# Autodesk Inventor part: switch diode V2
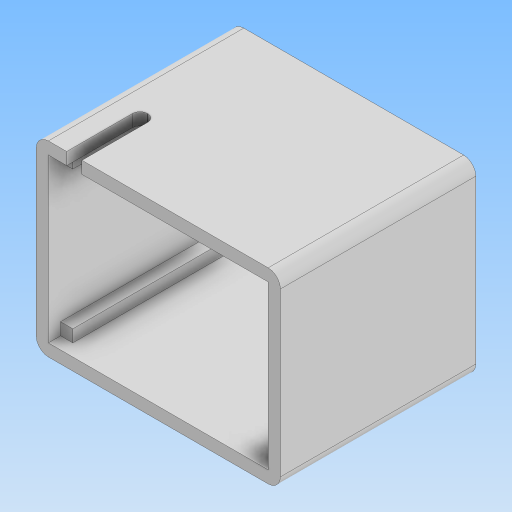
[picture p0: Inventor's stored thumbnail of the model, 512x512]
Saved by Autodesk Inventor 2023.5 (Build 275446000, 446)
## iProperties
Created: 2025-12
Part Number: switch diode V2
Material: Générique
Document SubType Name: Modeling
Designer: admin
Density: 1 g/cm^3
Appearance: Par défaut
Author: admin
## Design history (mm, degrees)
sketch "Esquisse1"
  geometry: L1 (28.6, 5.2)-(28.6, -5.2); L2 (-2.787, 5.2)-(2.787, 5.2); L3 (17.213, 5.2)-(22.787, 5.2); L4 (28.6, -5.2)-(17.213, -5.2); L5 (2.787, -5.2)-(-2.787, -5.2); L6 (-10, 20.648)-(30, 20.648); L7 (30, 20.648)-(30, -10); L8 (30, -10)-(-10, -10); L9 (-10, -10)-(-10, 20.648); L10 (20, 0)-(0, 0); L11 (10, 0)-(10, 20.648); C1 r 3.2 at (10, 12); A1 r 5.9 centre (0, 0) between (-2.787, 5.2) and (-2.787, -5.2); A2 r 5.9 centre (0, 0) between (2.787, -5.2) and (2.787, 5.2); A3 r 5.9 centre (20, 0) between (22.787, -5.2) and (22.787, 5.2); A4 r 5.9 centre (20, 0) between (17.213, 5.2) and (17.213, -5.2); 1 further point
  constraints: 22 end point, 8 point on circle, 6 parallel, 5 centre point, 3 horizontal, 3 perpendicular, 2 midpoint, 2 point on line, 1 coincident
  dimensions: "d2" = 20 distance of L10.start point (0, 0); "d3" = 10.4 distance of L1.start L1.end; "d5" = 0 vertical distance of point (0, 0) L10.start; "d6" = 40 distance of L7.end L8.end; "d7" = 10 distance from line of L10.end L9; "d8" = 10 distance from line of L7 L10.start (derived); "d9" = 10 distance from line of L8 point (0, 0); "d10" = 6.4 diameter of C1; "d11" = 12 vertical distance of point (0, 0) C1.centre
extrude "Extrusion1" new body sketch "Esquisse1" distance "d12" = 2; taper "d13" = 0 deg
sketch "Esquisse2"
  geometry: L1 (-10, -10)-(30, -10) reference; L2 (30, -10)-(30, 20.648) reference; L3 (30, 20.648)-(-10, 20.648) reference; L4 (-10, 20.648)-(-10, -10) reference; L5 (2.787, -5.2)-(-2.787, -5.2) reference; L6 (-2.787, 5.2)-(2.787, 5.2) reference; L7 (22.787, -5.2)-(17.213, -5.2) reference; L8 (17.213, 5.2)-(22.787, 5.2) reference; L9 (-8, 18.648)-(28, 18.648); L10 (28, 18.648)-(28, -8); L11 (28, -8)-(-8, -8); L12 (-8, -8)-(-8, 18.648); C1 r 3.2 at (10, 12) reference; A1 r 5.9 centre (0, 0) between (-2.787, 5.2) and (-2.787, -5.2) reference; A2 r 5.9 centre (0, 0) between (2.787, -5.2) and (2.787, 5.2) reference; A3 r 5.9 centre (20, 0) between (17.213, 5.2) and (17.213, -5.2) reference; A4 r 5.9 centre (20, 0) between (22.787, -5.2) and (22.787, 5.2) reference; 1 further point
  constraints: 8 end point, 2 parallel, 1 horizontal, 1 perpendicular
  dimensions: "d14" = 2 distance between parallel lines of L1 L11; "d15" = 2 distance between parallel lines of L2 L10; "d16" = 2 distance between parallel lines of L4 L12; "d17" = 2 distance between parallel lines of L3 L9
extrude "Extrusion2" join sketch "Esquisse2" distance "d18" = 30; taper "d19" = 0 deg
sketch "Esquisse3"
  geometry: L1 (40, -32)-(0, -32) reference; L2 (5, -32)-(7.5, -32); L3 (7.5, -32)-(7.5, -20); L4 (7.5, -20)-(5, -20); L5 (5, -20)-(5, -32); L6 (0, 0)-(0, -32) reference; 2 further points
  constraints: 8 end point, 2 parallel, 1 horizontal, 1 perpendicular, 1 point on line
  dimensions: "d20" = 2.5 distance of L3.end L4.end; "d21" = 12 distance of L4.end L2.start; "d47" = 5 distance between parallel lines of L6 L5
extrude "Extrusion3" cut sketch "Esquisse3" distance "d22" = 5; taper "d23" = 0 deg
fillet "Congé1" dims "d24" = 1.2
sketch "Esquisse4"
  geometry: L1 (10, -10)-(-30, -10) reference; L2 (10, 20.648)-(10, -10) reference; L3 (-30, 20.648)-(10, 20.648) reference; L4 (-30, -10)-(-30, 20.648) reference; L5 (-2.787, -5.2)-(2.787, -5.2) reference; L6 (2.787, 5.2)-(-2.787, 5.2) reference; L7 (-22.787, -5.2)-(-17.213, -5.2) reference; L8 (-17.213, 5.2)-(-22.787, 5.2) reference; L9 (-25.991, 15.856)-(-23.242, 15.856); L10 (-23.242, 15.856)-(-23.242, 12.744); L11 (-23.242, 12.744)-(-25.991, 12.744); L12 (-25.991, 12.744)-(-25.991, 15.856); L13 (2.122, 12.609)-(2.122, 15.87); L14 (2.122, 15.87)-(4.871, 15.87); L15 (4.871, 15.87)-(4.871, 12.609); L16 (4.871, 12.609)-(2.122, 12.609); C1 r 3.2 at (-10, 12) reference; A1 r 5.9 centre (0, 0) between (-2.787, 5.2) and (-2.787, -5.2) reference; A2 r 5.9 centre (0, 0) between (2.787, -5.2) and (2.787, 5.2) reference; A3 r 5.9 centre (-20, 0) between (-22.787, 5.2) and (-22.787, -5.2) reference; A4 r 5.9 centre (-20, 0) between (-17.213, -5.2) and (-17.213, 5.2) reference; 1 further point
  constraints: 4 other
extrude "Extrusion4" cut sketch "Esquisse4" extent not by distance; stored distance "d25" = 0; taper "d26" = 0 deg
sketch "Esquisse5"
  geometry: L1 (20.428, 12.029)-(20.428, 15.856) reference; L2 (20.428, 15.856)-(21.936, 15.856) reference; L3 (21.936, 15.856)-(21.936, 12.112) reference; L4 (23.949, 12.112)-(23.949, 15.856) reference; L5 (23.949, 15.856)-(25.456, 15.856) reference; L6 (25.456, 15.856)-(25.456, 12.024) reference; L7 (-5.73, 9.87)-(-5.73, 10.916) reference; L8 (-5.73, 10.916)-(-4.869, 10.916) reference; L9 (-4.869, 10.916)-(-4.869, 14.825) reference; L10 (-4.869, 14.825)-(-5.73, 14.825) reference; L11 (-5.73, 14.825)-(-5.73, 15.87) reference; L12 (-5.73, 15.87)-(-2.501, 15.87) reference; L13 (-2.501, 15.87)-(-2.501, 14.825) reference; L14 (-2.501, 14.825)-(-3.362, 14.825) reference; L15 (-3.362, 14.825)-(-3.362, 10.916) reference; L16 (-3.362, 10.916)-(-2.501, 10.916) reference; L17 (-2.501, 10.916)-(-2.501, 9.87) reference; L18 (-2.501, 9.87)-(-5.73, 9.87) reference; L19 (-8, 18.648)-(-8, -8) reference; L20 (-8, -8)-(28, -8) reference; L21 (28, -8)-(28, 18.648) reference; L22 (28, 18.648)-(-8, 18.648) reference; L23 (2.787, -5.2)-(-2.787, -5.2) reference; L24 (-2.787, 5.2)-(2.787, 5.2) reference; L25 (22.787, -5.2)-(17.213, -5.2) reference; L26 (17.213, 5.2)-(22.787, 5.2) reference; L27 (15, 6.2)-(5, 6.2); L28 (5, 6.2)-(5, 17.8); L29 (5, 17.8)-(15, 17.8); L30 (15, 17.8)-(15, 6.2); L31 (28, 18.648)-(-8, 18.648) reference; L32 (15.5, 17.8)-(4.5, 17.8); L33 (4.5, 17.8)-(4.5, 18.648); L34 (4.5, 18.648)-(15.5, 18.648); L35 (15.5, 18.648)-(15.5, 17.8); L36 (15.5, 6.2)-(4.5, 6.2); L37 (4.5, 6.2)-(4.5, 4.2); L38 (4.5, 4.2)-(15.5, 4.2); L39 (15.5, 4.2)-(15.5, 6.2); C1 r 3.2 at (10, 12) reference; A1 r 5.9 centre (0, 0) between (-2.787, 5.2) and (-2.787, -5.2) reference; A2 r 5.9 centre (0, 0) between (2.787, -5.2) and (2.787, 5.2) reference; A3 r 5.9 centre (20, 0) between (17.213, 5.2) and (17.213, -5.2) reference; A4 r 5.9 centre (20, 0) between (22.787, -5.2) and (22.787, 5.2) reference; 11 further points
  constraints: 24 end point, 6 parallel, 3 horizontal, 3 perpendicular, 3 point on line, 2 midpoint, 4 other
  dimensions: "d27" = 11.6 distance of L27.end L28.end; "d28" = 5.8 distance from line of L27 C1.centre (= 0.5 x d27); "d29" = 10 distance of L28.end L29.end; "d30" = 5 distance from line of C1.centre L30 (= 0.5 x d29); "d31" = 2 distance between parallel lines of L27 L38; "d32" = 11 distance of L37.end L38.end; "d33" = 11 distance of L32.start L32.end; "d34" = 5.5 horizontal distance of C1.centre point (4.5, 18.224) (= 0.5 x d33); "d35" = 5.5 horizontal distance of C1.centre point (15.5, 5.2) (= 0.5 x d32)
extrude "Extrusion5" join sketch "Esquisse5" distance "d36" = 13; taper "d37" = 0 deg
sketch "Esquisse6"
  geometry: L1 (22.787, -5.2)-(17.213, -5.2) reference; L2 (17.213, 5.2)-(22.787, 5.2) reference; L3 (2.787, -5.2)-(-2.787, -5.2) reference; L4 (-2.787, 5.2)-(2.787, 5.2) reference; L5 (15.5, 18.648)-(15.5, 17.8) reference; L6 (15.5, 17.8)-(4.5, 17.8) reference; L7 (4.5, 17.8)-(4.5, 18.648) reference; L8 (4.5, 18.648)-(-8, 18.648) reference; L9 (-8, 18.648)-(-8, -8) reference; L10 (-8, -8)-(28, -8) reference; L11 (28, -8)-(28, 18.648) reference; L12 (28, 18.648)-(15.5, 18.648) reference; L13 (-5.73, 9.87)-(-5.73, 10.916) reference; L14 (-5.73, 10.916)-(-4.869, 10.916) reference; L15 (-4.869, 10.916)-(-4.869, 14.825) reference; L16 (-4.869, 14.825)-(-5.73, 14.825) reference; L17 (-5.73, 14.825)-(-5.73, 15.87) reference; L18 (-5.73, 15.87)-(-2.501, 15.87) reference; L19 (-2.501, 15.87)-(-2.501, 14.825) reference; L20 (-2.501, 14.825)-(-3.362, 14.825) reference; L21 (-3.362, 14.825)-(-3.362, 10.916) reference; L22 (-3.362, 10.916)-(-2.501, 10.916) reference; L23 (-2.501, 10.916)-(-2.501, 9.87) reference; L24 (-2.501, 9.87)-(-5.73, 9.87) reference; L25 (20.428, 12.029)-(20.428, 15.856) reference; L26 (20.428, 15.856)-(21.936, 15.856) reference; L27 (21.936, 15.856)-(21.936, 12.112) reference; L28 (23.949, 12.112)-(23.949, 15.856) reference; L29 (23.949, 15.856)-(25.456, 15.856) reference; L30 (25.456, 15.856)-(25.456, 12.024) reference; L31 (15.5, 6.2)-(15.5, 4.2) reference; L32 (15.5, 4.2)-(4.5, 4.2) reference; L33 (4.5, 4.2)-(4.5, 6.2) reference; L34 (4.5, 6.2)-(15.5, 6.2) reference; L35 (4.5, 17.8)-(15.5, 17.8); L36 (15.5, 17.8)-(15.5, 6.2); L37 (15.5, 6.2)-(4.5, 6.2); L38 (4.5, 6.2)-(4.5, 17.8); C1 r 3.2 at (10, 12) reference; C2 r 3.2 at (10, 12) reference; A1 r 5.9 centre (20, 0) between (17.213, 5.2) and (17.213, -5.2) reference; A2 r 5.9 centre (20, 0) between (22.787, -5.2) and (22.787, 5.2) reference; A3 r 5.9 centre (0, 0) between (-2.787, 5.2) and (-2.787, -5.2) reference; A4 r 5.9 centre (0, 0) between (2.787, -5.2) and (2.787, 5.2) reference; 5 further points
  constraints: 8 end point, 2 parallel, 1 horizontal, 1 perpendicular, 4 other
extrude "Extrusion6" join sketch "Esquisse6" distance "d38" = 4; taper "d39" = 0 deg
sketch "Esquisse7"
  geometry: L1 (-8, 18.648)-(-8, -8) reference; L2 (-8, -8)-(-6, -8); L3 (-6, -8)-(-6, -6); L4 (-6, -6)-(-8, -6); L5 (-8, -6)-(-8, -8); L6 (-8, 18.648)-(-6, 18.648); L7 (-6, 18.648)-(-6, 16.648); L8 (-6, 16.648)-(-8, 16.648); L9 (-8, 16.648)-(-8, 18.648); L10 (28, -8)-(28, 18.648) reference; L11 (28, -8)-(26, -8); L12 (26, -8)-(26, -6); L13 (26, -6)-(28, -6); L14 (28, -6)-(28, -8); L15 (28, 18.648)-(26, 18.648); L16 (26, 18.648)-(26, 16.648); L17 (26, 16.648)-(28, 16.648); L18 (28, 16.648)-(28, 18.648); 6 further points
  constraints: 32 end point, 8 parallel, 4 horizontal, 4 perpendicular, 2 point on line
  dimensions: "d40" = 2 distance of L4.end L3.end; "d41" = 2 distance of L7.end L8.end; "d42" = 2 distance of L2.end L3.end; "d43" = 2 distance of L6.end L7.end; "d44" = 2 distance of L12.end L13.end
extrude "Extrusion7" join sketch "Esquisse7" distance "d45" = 28; taper "d46" = 0 deg
fillet "Congé2" dims "d48" = 2
sketch "Esquisse8"
  geometry: L1 (-3, -6)-(-3, -7); L2 (-17, -7)-(-17, -6); L3 (-15.5, 4.2)-(-4.5, 4.2) reference; L4 (10, 18.648)-(10, -8) reference; L5 (-28, 20.648)-(8, 20.648) reference; L6 (-30, -8)-(-30, 18.648) reference; L7 (8, -10)-(-28, -10) reference; L8 (-25.456, 12.024)-(-25.456, 15.856) reference; L9 (-25.456, 15.856)-(-23.949, 15.856) reference; L10 (-23.949, 15.856)-(-23.949, 12.112) reference; L11 (-21.936, 12.112)-(-21.936, 15.856) reference; L12 (-21.936, 15.856)-(-20.428, 15.856) reference; L13 (-20.428, 15.856)-(-20.428, 12.029) reference; L14 (5.73, 10.916)-(5.73, 9.87) reference; L15 (5.73, 9.87)-(2.501, 9.87) reference; L16 (2.501, 9.87)-(2.501, 10.916) reference; L17 (2.501, 10.916)-(3.362, 10.916) reference; L18 (3.362, 10.916)-(3.362, 14.825) reference; L19 (3.362, 14.825)-(2.501, 14.825) reference; L20 (2.501, 14.825)-(2.501, 15.87) reference; L21 (2.501, 15.87)-(5.73, 15.87) reference; L22 (5.73, 15.87)-(5.73, 14.825) reference; L23 (5.73, 14.825)-(4.869, 14.825) reference; L24 (4.869, 14.825)-(4.869, 10.916) reference; L25 (4.869, 10.916)-(5.73, 10.916) reference; L26 (-2.787, -5.2)-(2.787, -5.2) reference; L27 (2.787, 5.2)-(-2.787, 5.2) reference; L28 (-22.787, -5.2)-(-17.213, -5.2) reference; L29 (-17.213, 5.2)-(-22.787, 5.2) reference; L30 (-12, -9)-(-8.908, -7); L31 (-8.908, -6)-(-12, -4); L32 (-8.908, -4)-(-7.908, -4); L33 (-7.908, -9)-(-8.908, -9); L34 (-17, -6)-(-12, -6); L35 (-12, -4)-(-12, -6); L36 (-12, -7)-(-12, -9); L37 (-12, -7)-(-17, -7); L38 (-8.908, -9)-(-8.908, -7); L39 (-8.908, -6)-(-8.908, -4); L40 (-7.908, -4)-(-7.908, -6); L41 (-7.908, -7)-(-7.908, -9); L42 (-8.908, -6)-(-8.908, -6); L43 (-7.908, -6)-(-3, -6); L44 (-3, -7)-(-7.908, -7); C1 r 3.2 at (-10, 12) reference; A1 r 2 centre (8, -8) between (8, -10) and (10, -8) reference; A2 r 2 centre (8, 18.648) between (10, 18.648) and (8, 20.648) reference; A3 r 2 centre (-28, 18.648) between (-28, 20.648) and (-30, 18.648) reference; A4 r 2 centre (-28, -8) between (-30, -8) and (-28, -10) reference; A5 r 5.9 centre (0, 0) between (-2.787, 5.2) and (-2.787, -5.2) reference; A6 r 5.9 centre (0, 0) between (2.787, -5.2) and (2.787, 5.2) reference; A7 r 5.9 centre (-20, 0) between (-22.787, 5.2) and (-22.787, -5.2) reference; A8 r 5.9 centre (-20, 0) between (-17.213, -5.2) and (-17.213, 5.2) reference; 6 further points; 1 other entity
  constraints: 34 end point, 12 parallel, 7 horizontal, 5 perpendicular, 2 vertical, 1 coincident, 1 midpoint, 6 other
  dimensions: "d50" = 14 distance of L1.end L2.start; "d54" = 5 distance of L31.end L30.start; "d55" = 2.5 vertical distance of L31.end point (-17, -6.5); "d65" = 5 distance from line of point (-17, -6.5) L35; "d66" = 13 distance from line of L6 point (-17, -6.5)
extrude "Extrusion8" cut sketch "Esquisse8" distance "d61" = 13; taper "d62" = 0 deg
sketch "Esquisse9"
  geometry: L1 (20, 30)-(20, 19) reference; L2 (20, 19)-(18.454, 19) reference; L3 (18.454, 19)-(18.454, 30) reference; L4 (16.908, 30)-(18.454, 30) reference; L5 (16.908, 30)-(16.908, 19) reference; L6 (16.908, 19)-(15.908, 19) reference; L7 (15.908, 19)-(15.908, 30) reference; L8 (2, 30)-(15.908, 30) reference; L9 (2, 30)-(2, 2) reference; L10 (2, 2)-(0, 2) reference; L11 (0, 2)-(0, 0) reference; L12 (36, 0)-(0, 0) reference; L13 (36, 2)-(36, 0) reference; L14 (36, 2)-(34, 2) reference; L15 (34, 2)-(34, 30) reference; L16 (20, 30)-(34, 30) reference; L17 (15.908, 19)-(15.908, 30) reference; L18 (20, 32)-(20, 19) reference; L19 (15.908, 30)-(20, 30); L20 (20, 30)-(20, 19); L21 (20, 19)-(15.908, 19); L22 (15.908, 19)-(15.908, 30); 4 further points
  constraints: 8 end point, 2 parallel, 1 horizontal, 1 perpendicular
extrude "Extrusion9" join sketch "Esquisse9" distance "d63" = 2; taper "d64" = 0 deg
sketch "Esquisse10"
  geometry: L1 (15.5, 6.2)-(4.5, 6.2) reference; L2 (15.5, 6.2)-(15.5, 17.8) reference; L3 (4.5, 17.8)-(15.5, 17.8) reference; L4 (4.5, 17.8)-(4.5, 6.2) reference; C1 r 3.2 at (10, 12) reference; C2 r 4.25 at (10, 12); 1 further point
  constraints: 1 centre point, 1 coincident
  dimensions: "d67" = 8.5 diameter of C2
extrude "Extrusion10" cut sketch "Esquisse10" distance "d68" = 1; taper "d69" = 0 deg
chamfer "Chanfrein1" distance "d70" = 1; stored, may be unused: second distance "d71" = 2, angle "d72" = 45 deg
node "Solide1"
node "Boucle projetée1"
node "Boucle projetée2"
node "Boucle projetée3"
node "Boucle projetée4"
node "Boucle projetée5"
node "Boucle projetée6"
node "Boucle projetée7"
other parameters: "d0" = 11.8, "d1" = 11.8, "d4" = 5.2 (= 0.5 x d3), "d49" = 1, "d51" = 6, "d56" = 5, "d57" = 1
